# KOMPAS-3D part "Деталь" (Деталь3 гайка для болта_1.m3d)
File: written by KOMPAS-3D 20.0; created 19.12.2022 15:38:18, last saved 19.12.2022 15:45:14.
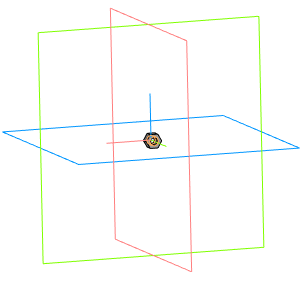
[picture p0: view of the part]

Document properties: Полное имя файла: C:\Users\Семья\Desktop\ДЕТАЛИ ДЛЯ СБОРЩИКА БОРЩЕВИКА\ДЕТАЛИ ДЛЯ ФИНАЛА\Деталь3 гайка для болта_1.m3d

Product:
- Part/product: Деталь
    Масса: 9.21622e-05

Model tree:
1. Эскиз:1
2. Элемент выдавливания:1
     Расстояние 1 = 2
3. Условное изображение резьбы:1  (with: Элемент выдавливания:1)  (labels: M2; cil0_24705-2004 coarse)
     Длина резьбы = 2; Шаг резьбы = 0.4; Номинальный диаметр резьбы = 2
4. Подгонка:1  (with: Элемент выдавливания:1)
